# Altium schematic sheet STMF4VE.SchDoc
size A2
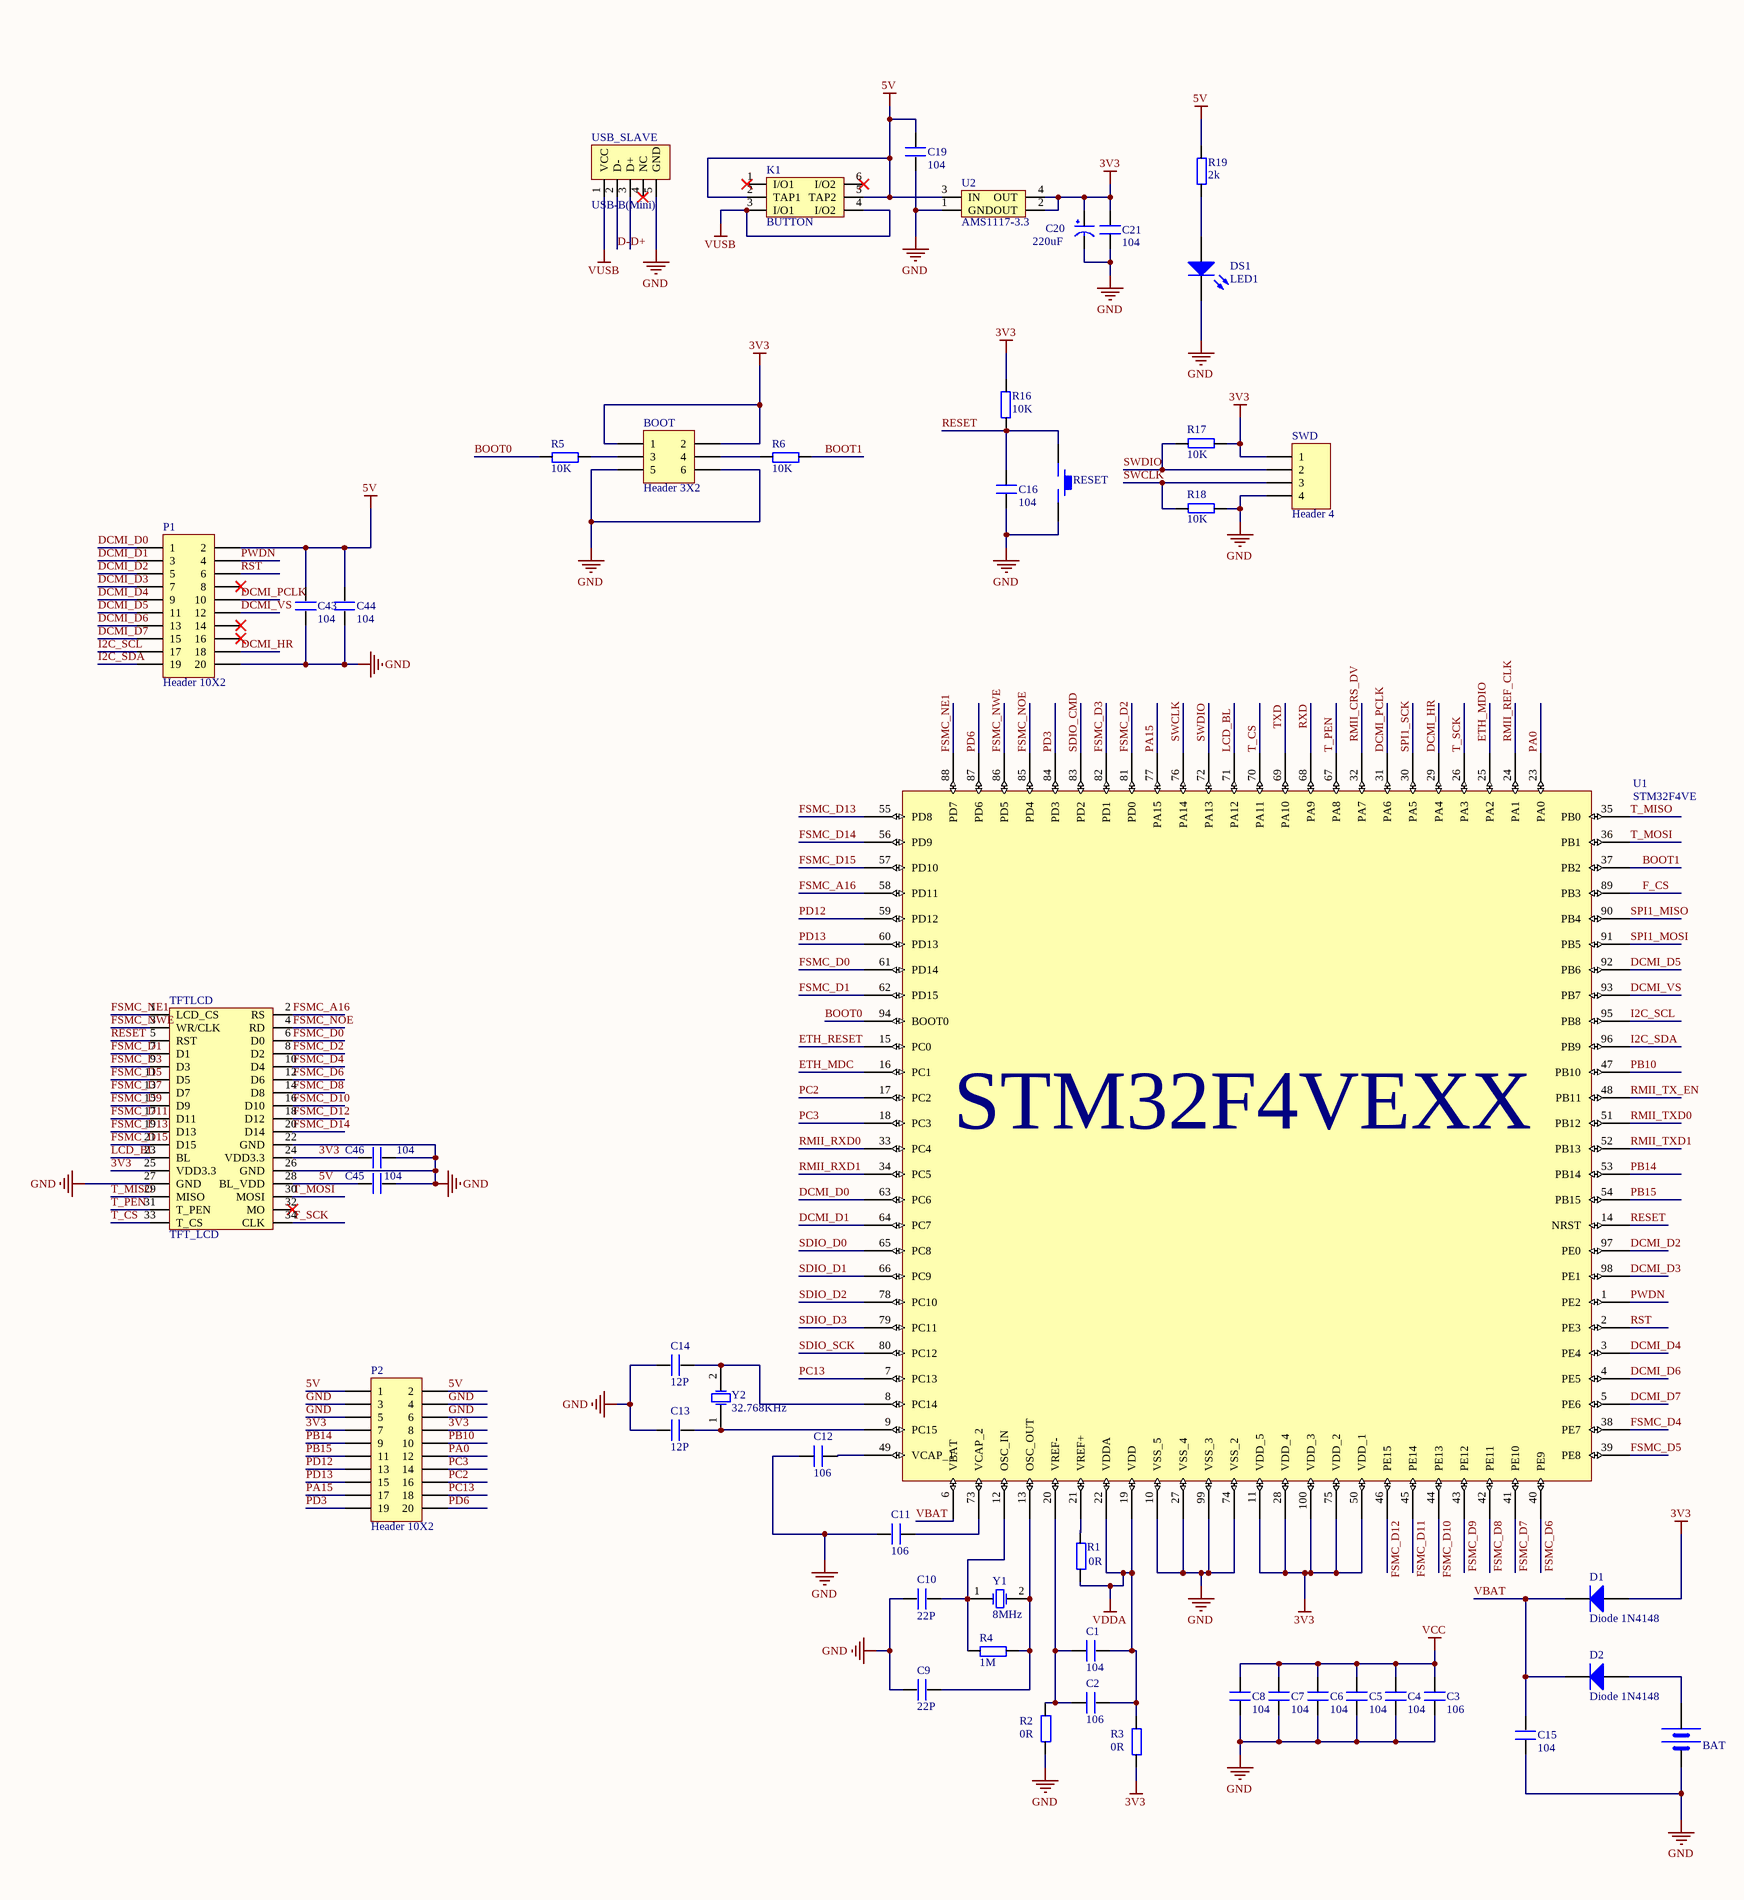
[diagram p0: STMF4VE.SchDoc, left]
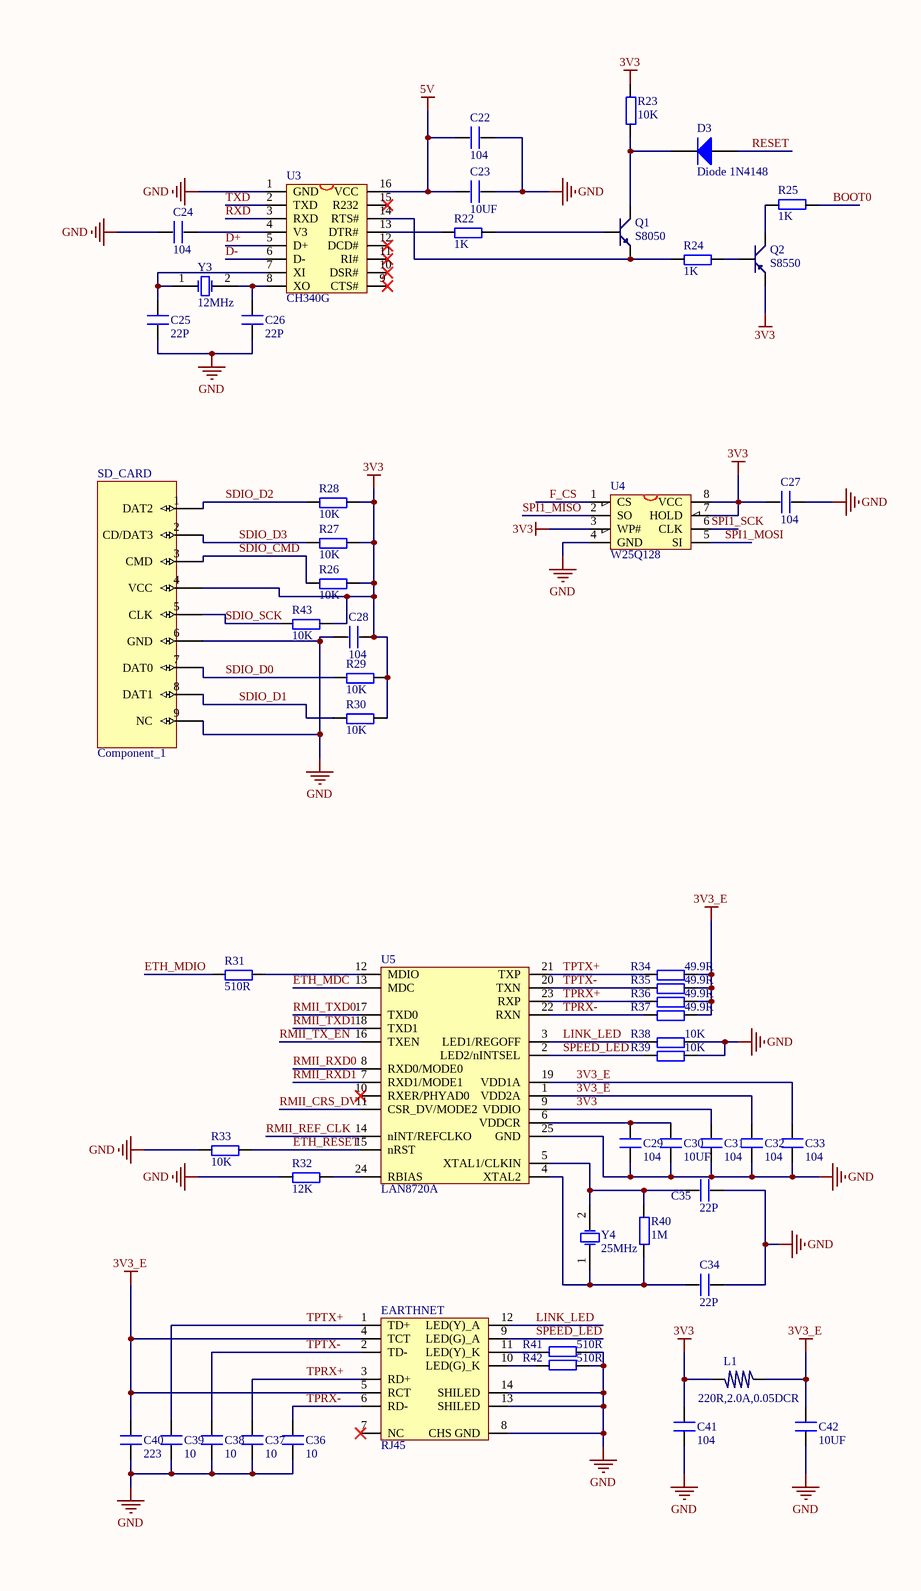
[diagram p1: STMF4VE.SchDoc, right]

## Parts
BAT  BATT  [BATM]  (value not drawn)
BOOT  Header 3X2  [HDR2X3]
C1  104  [0603P]
C2  106  [0805]
C3  106  [0805]
C4  104  [0603P]
C5  104  [0603P]
C6  104  [0603P]
C7  104  [0603P]
C8  104  [0603P]
C9  22P  [0603P]
C10  22P  [0603P]
C11  106  [0603P]
C12  106  [0603P]
C13  12P  [0603P]
C14  12P  [0603P]
C15  104  [0603P]
C16  104  [0603P]
C19  104  [0603P]
C20  220uF  [CC6.56.5]
C21  104  [0603P]
C22  104  [0603P]
C23  10UF  [0603P]
C24  104  [0603P]
C25  22P  [0603P]
C26  22P  [0603P]
C27  104  [0603P]
C28  104  [0603P]
C29  104  [0603P]
C30  10UF  [0603P]
C31  104  [0603P]
C32  104  [0603P]
C33  104  [0603P]
C34  22P  [0603P]
C35  22P  [0603P]
C36  10  [0603P]
C37  10  [0603P]
C38  10  [0603P]
C39  10  [0603P]
C40  223  [0603P]
C41  104  [0603P]
C42  10UF  [0603P]
C43  104  [0603P]
C44  104  [0603P]
C45  104  [0603P]
C46  104  [0603P]
D1  Diode 1N4148  [DO-35]
D2  Diode 1N4148  [DO-35]
D3  Diode 1N4148  [DO-35]
DS1  LED1  [SMDLED]
EARTHNET  RJ45  [HR911105A]
K1  BUTTON  [BTN8.5*8.5]
L1  220R,2.0A,0.05DCR  [0603P]
P1  Header 10X2  [HDR2X10]
P2  Header 10X2  [HDR2X10]
Q1  S8050  [SOT-23R]
Q2  S8550  [SOT-23R]
R1  0R  [0603P]
R2  0R  [0603P]
R3  0R  [0603P]
R4  1M  [0603P]
R5  10K  [0603P]
R6  10K  [0603P]
R16  10K  [0603P]
R17  10K  [0603P]
R18  10K  [0603P]
R19  2k  [0603P]
R22  1K  [0603P]
R23  10K  [0603P]
R24  1K  [0603P]
R25  1K  [0603P]
R26  10K  [0603P]
R27  10K  [0603P]
R28  10K  [0603P]
R29  10K  [0603P]
R30  10K  [0603P]
R31  510R  [0603P]
R32  12K  [0603P]
R33  10K  [0603P]
R34  49.9R  [0603P]
R35  49.9R  [0603P]
R36  49.9R  [0603P]
R37  49.9R  [0603P]
R38  10K  [0603P]
R39  10K  [0603P]
R40  1M  [0603P]
R41  510R  [0603P]
R42  510R  [0603P]
R43  10K  [0603P]
RESET  KEY_M  [KEY_M]  (value not drawn)
SD_CARD  Component_1  [TF_SD]
SWD  Header 4  [HDR1X4]
TFTLCD  TFT_LCD  [TFT_LCD]
U1  STM32F4VE  [LQFP100]
U2  AMS1117-3.3  [AMS1117]
U3  CH340G  [SOP16M]
U4  W25Q128  [SOIC-8]
U5  LAN8720A  [QFN24]
USB_SLAVE  USB-B(Mini)  [USB/SM0.8-6H5]
Y1  8MHz  [49S_SMD]
Y2  32.768KHz  [JZ32768]
Y3  12MHz  [49S_SMD]
Y4  25MHz  [49S_SMD]

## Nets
3V3: BOOT.1 BOOT.2 C20.1(VCC) C21.2 C27.1 C28.2 C31.2 C41.2 C46.1 D1.1(A) L1.2 P2.7 P2.8 Q2.1(E) R3.1 R16.1 R17.1 R23.2 R26.2 R27.2 R28.2 R29.2 R30.2 R43.2 SD_CARD.4(VCC) SWD.1 TFTLCD.24(VDD3.3) TFTLCD.25(VDD3.3) U1.11(VDD_5) U1.28(VDD_4) U1.50(VDD_1) U1.75(VDD_2) U1.100(VDD_3) U2.2(OUT) U2.4(OUT) U4.3(WP#) U4.7(HOLD) U4.8(VCC) U5.9(VDDIO)
3V3_E: C32.2 C33.2 C40.2 C42.2 EARTHNET.4(TCT) EARTHNET.5(RCT) L1.1 R34.2 R35.2 R36.2 R37.2 U5.1(VDD2A) U5.19(VDD1A)
5V: C19.1 C22.2 C23.1 C43.2 C44.2 C45.1 K1.2(TAP1) K1.5(TAP2) P1.2 P2.1 P2.2 R19.2 TFTLCD.28(BL_VDD) U2.3(IN) U3.16(VCC)
GND: BAT.2(GND) BOOT.5 BOOT.6 C3.1 C4.1 C5.1 C6.1 C7.1 C8.1 C9.2 C10.2 C11.1 C12.1 C13.1 C14.1 C15.1 C16.1 C19.2 C20.2(GND) C21.1 C22.1 C23.2 C24.1 C25.1 C26.1 C27.2 C28.1 C29.1 C30.1 C31.1 C32.1 C33.1 C34.2 C35.2 C36.1 C37.1 C38.1 C39.1 C40.1 C41.1 C42.1 C43.1 C44.1 C45.2 C46.2 DS1.2(K) EARTHNET.8(CHS_GND) EARTHNET.13(SHILED) EARTHNET.14(SHILED) P1.20 P2.3 P2.4 P2.5 P2.6 R2.1 R18.1 R32.1 R33.1 R38.2 R39.2 R41.1 R42.1 RESET.2 SD_CARD.6(GND) SD_CARD.9(NC) SWD.4 TFTLCD.22(GND) TFTLCD.26(GND) TFTLCD.27(GND) U1.10(VSS_5) U1.27(VSS_4) U1.74(VSS_2) U1.99(VSS_3) U2.1(GND) U3.1(GND) U4.4(GND) U5.25(GND) USB_SLAVE.5(GND)
VCC: C3.2 C4.2 C5.2 C6.2 C7.2 C8.2
VDDA: C1.2 C2.2 R1.1 R3.2 U1.19(VDD) U1.22(VDDA)
VUSB: K1.3(I/O1) K1.4(I/O2) USB_SLAVE.1(VCC)
BOOT0: R5.1 R25.1 U1.94(BOOT0)
BOOT1: R6.2 U1.37(PB2)
D+: U3.5(D+) USB_SLAVE.3(D+)
D-: U3.6(D-) USB_SLAVE.2(D-)
DCMI_D0: P1.1 U1.63(PC6)
DCMI_D1: P1.3 U1.64(PC7)
DCMI_D2: P1.5 U1.97(PE0)
DCMI_D3: P1.7 U1.98(PE1)
DCMI_D4: P1.9 U1.3(PE4)
DCMI_D5: P1.11 U1.92(PB6)
DCMI_D6: P1.13 U1.4(PE5)
DCMI_D7: P1.15 U1.5(PE6)
DCMI_HR: P1.18 U1.29(PA4)
DCMI_PCLK: P1.10 U1.31(PA6)
DCMI_VS: P1.12 U1.93(PB7)
ETH_MDC: U1.16(PC1) U5.13(MDC)
ETH_MDIO: R31.1 U1.25(PA2)
ETH_RESET: R33.2 U1.15(PC0) U5.15(nRST)
F_CS: U1.89(PB3) U4.1(CS)
FSMC_A16: TFTLCD.2(RS) U1.58(PD11)
FSMC_D0: TFTLCD.6(D0) U1.61(PD14)
FSMC_D1: TFTLCD.7(D1) U1.62(PD15)
FSMC_D2: TFTLCD.8(D2) U1.81(PD0)
FSMC_D3: TFTLCD.9(D3) U1.82(PD1)
FSMC_D4: TFTLCD.10(D4) U1.38(PE7)
FSMC_D5: TFTLCD.11(D5) U1.39(PE8)
FSMC_D6: TFTLCD.12(D6) U1.40(PE9)
FSMC_D7: TFTLCD.13(D7) U1.41(PE10)
FSMC_D8: TFTLCD.14(D8) U1.42(PE11)
FSMC_D9: TFTLCD.15(D9) U1.43(PE12)
FSMC_D10: TFTLCD.16(D10) U1.44(PE13)
FSMC_D11: TFTLCD.17(D11) U1.45(PE14)
FSMC_D12: TFTLCD.18(D12) U1.46(PE15)
FSMC_D13: TFTLCD.19(D13) U1.55(PD8)
FSMC_D14: TFTLCD.20(D14) U1.56(PD9)
FSMC_D15: TFTLCD.21(D15) U1.57(PD10)
FSMC_NE1: TFTLCD.1(LCD_CS) U1.88(PD7)
FSMC_NOE: TFTLCD.4(RD) U1.85(PD4)
FSMC_NWE: TFTLCD.3(WR/CLK) U1.86(PD5)
I2C_SCL: P1.17 U1.95(PB8)
I2C_SDA: P1.19 U1.96(PB9)
LCD_BL: TFTLCD.23(BL) U1.71(PA12)
LINK_LED: EARTHNET.12(LED(Y)_A) R38.1 U5.3(LED1/REGOFF)
PA0: P2.12 U1.23(PA0)
PA15: P2.17 U1.77(PA15)
PB10: P2.10 U1.47(PB10)
PB14: P2.9 U1.53(PB14)
PB15: P2.11 U1.54(PB15)
PC2: P2.16 U1.17(PC2)
PC3: P2.14 U1.18(PC3)
PC13: P2.18 U1.7(PC13)
PD3: P2.19 U1.84(PD3)
PD6: P2.20 U1.87(PD6)
PD12: P2.13 U1.59(PD12)
PD13: P2.15 U1.60(PD13)
PWDN: P1.4 U1.1(PE2)
RESET: C16.2 D3.1(A) R16.2 RESET.1 TFTLCD.5(RST) U1.14(NRST)
RMII_CRS_DV: U1.32(PA7) U5.11(CSR_DV/MODE2)
RMII_REF_CLK: U1.24(PA1) U5.14(nINT/REFCLKO)
RMII_RXD0: U1.33(PC4) U5.8(RXD0/MODE0)
RMII_RXD1: U1.34(PC5) U5.7(RXD1/MODE1)
RMII_TX_EN: U1.48(PB11) U5.16(TXEN)
RMII_TXD0: U1.51(PB12) U5.17(TXD0)
RMII_TXD1: U1.52(PB13) U5.18(TXD1)
RST: P1.6 U1.2(PE3)
RXD: U1.68(PA9) U3.3(RXD)
SDIO_CMD: R26.1 SD_CARD.3(CMD) U1.83(PD2)
SDIO_D0: R29.1 SD_CARD.7(DAT0) U1.65(PC8)
SDIO_D1: R30.1 SD_CARD.8(DAT1) U1.66(PC9)
SDIO_D2: R28.1 SD_CARD.1(DAT2) U1.78(PC10)
SDIO_D3: R27.1 SD_CARD.2(CD/DAT3) U1.79(PC11)
SDIO_SCK: R43.1 SD_CARD.5(CLK) U1.80(PC12)
SPEED_LED: EARTHNET.9(LED(G)_A) R39.1 U5.2(LED2/nINTSEL)
SPI1_MISO: U1.90(PB4) U4.2(SO)
SPI1_MOSI: U1.91(PB5) U4.5(SI)
SPI1_SCK: U1.30(PA5) U4.6(CLK)
SWCLK: R18.2 SWD.3 U1.76(PA14)
SWDIO: R17.2 SWD.2 U1.72(PA13)
T_CS: TFTLCD.33(T_CS) U1.70(PA11)
T_MISO: TFTLCD.29(MISO) U1.35(PB0)
T_MOSI: TFTLCD.30(MOSI) U1.36(PB1)
T_PEN: TFTLCD.31(T_PEN) U1.67(PA8)
T_SCK: TFTLCD.34(CLK) U1.26(PA3)
TPRX+: C37.2 EARTHNET.3(RD+) R36.1 U5.23(RXP)
TPRX-: C36.2 EARTHNET.6(RD-) R37.1 U5.22(RXN)
TPTX+: C39.2 EARTHNET.1(TD+) R34.1 U5.21(TXP)
TPTX-: C38.2 EARTHNET.2(TD-) R35.1 U5.20(TXN)
TXD: U1.69(PA10) U3.2(TXD)
VBAT: C15.2 D1.2(K) D2.2(K) U1.6(VBAT)
NetBAT_1: BAT.1(VCC) D2.1(A)
NetBOOT_3: BOOT.3 R5.2
NetBOOT_4: BOOT.4 R6.1
NetC1_1: C1.1 C2.1 R2.2 U1.20(VREF-)
NetC9_1: C9.1 R4.2 U1.13(OSC_OUT) Y1.2(OSC2)
NetC10_1: C10.1 R4.1 U1.12(OSC_IN) Y1.1(OSC1)
NetC11_2: C11.2 U1.73(VCAP_2)
NetC12_2: C12.2 U1.49(VCAP_1)
NetC13_2: C13.2 U1.9(PC15) Y2.1(OSC1)
NetC14_2: C14.2 U1.8(PC14) Y2.2(OSC2)
NetC24_2: C24.2 U3.4(V3)
NetC25_2: C25.2 U3.7(XI) Y3.1(OSC1)
NetC26_2: C26.2 U3.8(XO) Y3.2(OSC2)
NetC29_2: C29.2 C30.2 U5.6(VDDCR)
NetC34_1: C34.1 R40.1 U5.4(XTAL2) Y4.1(OSC1)
NetC35_1: C35.1 R40.2 U5.5(XTAL1/CLKIN) Y4.2(OSC2)
NetD3_2: D3.2(K) Q1.3(C) R23.1
NetDS1_1: DS1.1(A) R19.1
NetEARTHNET_10: EARTHNET.10(LED(G)_K) R42.2
NetEARTHNET_11: EARTHNET.11(LED(Y)_K) R41.2
NetQ1_1: Q1.1(E) R24.1 U3.14(RTS#)
NetQ1_2: Q1.2(B) R22.2
NetQ2_2: Q2.2(B) R24.2
NetQ2_3: Q2.3(C) R25.2
NetR1_2: R1.2 U1.21(VREF+)
NetR22_1: R22.1 U3.13(DTR#)
NetR31_2: R31.2 U5.12(MDIO)
NetR32_2: R32.2 U5.24(RBIAS)

Not connected (* = marked no-connect by the designer): EARTHNET 7(NC)*; K1 1(I/O1)* 6(I/O2)*; P1 8* 14* 16*; TFTLCD 32(MO)*; U3 9(CTS#)* 10(DSR#)* 11(RI#)* 12(DCD#)* 15(R232)*; U5 10(RXER/PHYAD0)*; USB_SLAVE 4(NC)*

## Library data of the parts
BAT = BAT
BOOT = Header 3X2: Header, 3-Pin, Dual row
C1-C16 C19 C21-C46 = C
C20 = CAP
D1-D3 = Diode 1N4148: High Conductance Fast Diode
DS1 = LED2: Typical RED, GREEN, YELLOW, AMBER GaAs LED
EARTHNET = HR911105
L1 = L
P1 P2 = Header 10X2: Header, 10-Pin, Dual row
Q1 = NPN: 8050/BCW846/BCW847
Q2 = PNP: 8550/BCW68
R1-R6 R16-R19 R22-R43 = R
SWD = Header 4: Header, 4-Pin
U2 = AMS1117
U3 = CH340G: USB2UART
U4 = W25X16: W25X16;SST25VF016;MX25L1605
U5 = LAN8720: ETH PHY
USB_SLAVE = USB5
Y1-Y4 = XTAL: Crystal Oscillator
